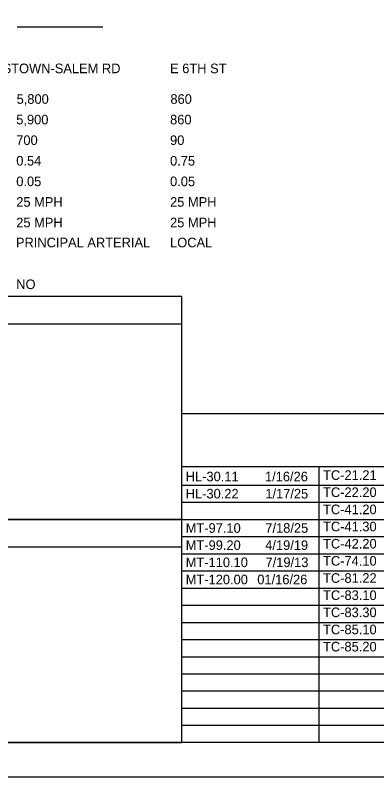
# Model space of a CAD drawing. Extents: x 0 to 34, y 0 to 22.
# Drawn here: x 7.72 to 12.99, y 0 to 11.1 of the extents above; entities that cross this region are included whole.
import ezdxf

# ---------------------------------------------------------------- set-up
doc = ezdxf.new("R2010")
doc.units = 0
for name, color, linetype in [('Default', 7, 'Continuous'), ('SH_Border', 7, 'Continuous'), ('SH_Cut_Line', 7, 'Continuous'), ('SH_Data', 7, 'Continuous'), ('SH_Text', 7, 'Continuous')]:
    doc.layers.add(name, color=color, linetype=linetype)

msp = doc.modelspace()

# ---------------------------------------------------------------- linework, layer by layer
at = {"layer": 'SH_Border'}
msp.add_lwpolyline([(1.5, 21.5), (33.5, 21.5), (33.5, 0.5), (1.5, 0.5)], close=True, dxfattribs=at)
at = {"layer": 'SH_Cut_Line'}
msp.add_lwpolyline([(0, 0), (34, 0), (34, 22), (0, 22)], close=True, dxfattribs=at)
at = {"layer": 'SH_Data'}
for p, q in [((9, 10.922), (7.75, 10.922)), ((7.35, 6.6), (10.15, 6.6)), ((10.15, 5.292), (23.6, 5.292)), ((10.15, 0.5), (10.15, 5.292)), ((10.15, 4.521), (23.6, 4.521)), ((12.15, 0.5), (12.15, 4.521)), ((10.15, 4.25), (23.6, 4.25)), ((10.15, 4), (23.6, 4)), ((10.15, 3.75), (23.6, 3.75)), ((10.15, 3.5), (23.6, 3.5)), ((7.35, 3.35), (10.15, 3.35)), ((10.15, 3.25), (23.6, 3.25)), ((10.15, 3), (23.6, 3)), ((10.15, 2.75), (23.6, 2.75)), ((10.15, 2.5), (23.6, 2.5)), ((10.15, 2.25), (23.6, 2.25)), ((10.15, 2), (23.6, 2)), ((10.15, 1.75), (23.6, 1.75)), ((10.15, 1.5), (23.6, 1.5)), ((10.15, 1.25), (23.6, 1.25)), ((10.15, 1), (23.6, 1)), ((10.15, 0.75), (23.6, 0.75))]:
    msp.add_line(p, q, dxfattribs=at)
for points in [[(10.15, 7), (7.35, 7), (7.35, 3.75), (10.15, 3.75)], [(10.15, 3.75), (7.35, 3.75), (7.35, 0.5), (10.15, 0.5)]]:
    msp.add_lwpolyline(points, close=True, dxfattribs=at)

# ---------------------------------------------------------------- texts
at = {"layer": 'Default'}
for s, p in [('YOUNGSTOWN-SALEM RD', (6.852, 10.252)), ('E 6TH ST', (9.977, 10.252))]:
    msp.add_text(s, height=0.14, dxfattribs=at).set_placement(p)
at = {"layer": 'SH_Data'}
for s, p in [('PRINCIPAL ARTERIAL', (7.732, 7.715)), ('LOCAL', (9.977, 7.715))]:
    msp.add_text(s, height=0.14, dxfattribs=at).set_placement(p)
at = {"layer": 'SH_Text'}
for s, p in [('5,800', (7.742, 9.806)), ('860', (9.982, 9.806)), ('5,900', (7.737, 9.506)), ('860', (9.977, 9.506)), ('700', (7.737, 9.206)), ('90', (9.977, 9.206)), ('0.54', (7.737, 8.906)), ('0.75', (9.977, 8.906)), ('0.05', (7.737, 8.606)), ('0.05', (9.977, 8.606)), ('25 MPH', (7.737, 8.306)), ('25 MPH', (9.977, 8.306)), ('25 MPH', (7.737, 8.006)), ('25 MPH', (9.977, 8.006)), ('NO', (7.737, 7.106)), ('HL-30.11', (10.205, 4.305)), ('1/16/26', (11.359, 4.305)), ('TC-21.21', (12.205, 4.326)), ('TC-22.20', (12.205, 4.076)), ('HL-30.22', (10.205, 4.055)), ('1/17/25', (11.364, 4.055)), ('TC-41.20', (12.205, 3.826)), ('MT-97.10', (10.205, 3.555)), ('7/18/25', (11.364, 3.555)), ('TC-41.30', (12.205, 3.576)), ('MT-99.20', (10.205, 3.305)), ('4/19/19', (11.363, 3.305)), ('TC-42.20', (12.205, 3.326)), ('MT-110.10', (10.205, 3.055)), ('7/19/13', (11.367, 3.055)), ('TC-74.10', (12.205, 3.076)), ('MT-120.00', (10.205, 2.805)), ('01/16/26', (11.247, 2.805)), ('TC-81.22', (12.205, 2.826)), ('TC-83.10', (12.205, 2.576)), ('TC-83.30', (12.205, 2.326)), ('TC-85.10', (12.205, 2.076)), ('TC-85.20', (12.205, 1.826))]:
    msp.add_text(s, height=0.14, dxfattribs=at).set_placement(p)

doc.saveas('drawing.dxf')
